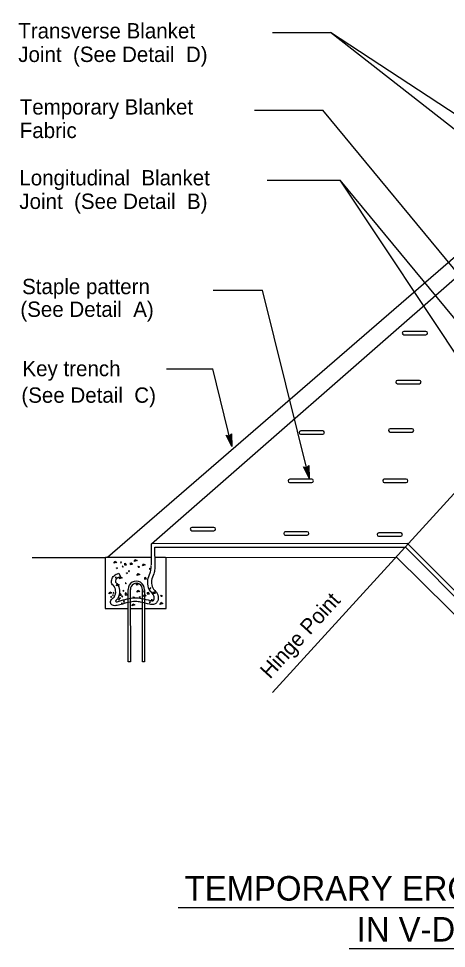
# Model space of a CAD drawing. Extents: x 6712486 to 6713732, y 1869200 to 1869925.
# Drawn here: x 6712488.9 to 6712663, y 1869199.8 to 1869578.2 of the extents above; entities that cross this region are included whole.
import ezdxf

# ---------------------------------------------------------------- set-up
doc = ezdxf.new("R2010")
doc.units = 0
for name, color, linetype in [('56 Stg 3 Anno', 7, 'Continuous'), ('57 Undefined', 7, 'Continuous'), ('60 Nongeo Data', 7, 'Continuous'), ('63 Undefined', 7, 'Continuous')]:
    doc.layers.add(name, color=color, linetype=linetype)

msp = doc.modelspace()

# ---------------------------------------------------------------- linework, layer by layer
at = {"layer": '56 Stg 3 Anno'}
for p, q in [((6712575.73, 1869404.07), (6712573.4, 1869408.62)), ((6712573.4, 1869408.62), (6712573.4, 1869408.62)), ((6712573.4, 1869408.62), (6712574.64, 1869408.26)), ((6712575.43, 1869405.19), (6712573.74, 1869408.51)), ((6712575.15, 1869406.29), (6712574.05, 1869408.44)), ((6712574.86, 1869407.41), (6712574.39, 1869408.32)), ((6712574.64, 1869408.26), (6712575.55, 1869409.18)), ((6712574.83, 1869408.45), (6712574.86, 1869407.41)), ((6712575.07, 1869408.67), (6712575.15, 1869406.29)), ((6712575.31, 1869408.93), (6712575.44, 1869405.18)), ((6712575.55, 1869409.18), (6712575.55, 1869409.18)), ((6712575.55, 1869409.18), (6712575.73, 1869404.07)), ((6712575.73, 1869404.07), (6712575.73, 1869404.07)), ((6712607.13, 1869391.15), (6712604.8, 1869395.7)), ((6712604.8, 1869395.7), (6712604.8, 1869395.7)), ((6712604.8, 1869395.7), (6712606.04, 1869395.34)), ((6712606.83, 1869392.27), (6712605.14, 1869395.59)), ((6712606.55, 1869393.37), (6712605.45, 1869395.52)), ((6712606.26, 1869394.49), (6712605.79, 1869395.41)), ((6712606.04, 1869395.34), (6712606.95, 1869396.26)), ((6712606.22, 1869395.54), (6712606.26, 1869394.49)), ((6712606.47, 1869395.75), (6712606.55, 1869393.37)), ((6712606.71, 1869396.01), (6712606.84, 1869392.26)), ((6712606.95, 1869396.26), (6712606.95, 1869396.26)), ((6712606.95, 1869396.26), (6712607.13, 1869391.15)), ((6712607.13, 1869391.15), (6712607.13, 1869391.15))]:
    msp.add_line(p, q, dxfattribs=at)
at = {"layer": '57 Undefined'}
for p, q in [((6712553.77, 1869216.45), (6712862.41, 1869216.45)), ((6712623.47, 1869199.8), (6712793.24, 1869199.8))]:
    msp.add_line(p, q, dxfattribs=at)
at = {"layer": '60 Nongeo Data'}
for p, q in [((6712525.01, 1869359), (6712778.34, 1869578.13)), ((6712592.16, 1869303.9), (6712842.3, 1869578.16)), ((6712592.17, 1869572.5), (6712615.77, 1869572.5)), ((6712716.02, 1869494.14), (6712615.77, 1869572.5)), ((6712724.97, 1869500.98), (6712615.77, 1869572.5)), ((6712584.88, 1869540.92), (6712612.7, 1869540.92)), ((6712695.74, 1869440.43), (6712612.7, 1869540.92)), ((6712590, 1869512.45), (6712619.78, 1869512.45)), ((6712707.85, 1869379.8), (6712619.78, 1869512.45)), ((6712711.19, 1869401.83), (6712619.78, 1869512.45)), ((6712542.99, 1869364.46), (6712696.56, 1869498.79)), ((6712568.01, 1869467.69), (6712588.18, 1869467.69)), ((6712607.13, 1869391.15), (6712588.18, 1869467.69)), ((6712654.67, 1869450.88), (6712645.71, 1869450.88)), ((6712645.65, 1869449.51), (6712654.67, 1869449.51)), ((6712549.02, 1869435.61), (6712567.92, 1869435.61)), ((6712575.73, 1869404.07), (6712567.92, 1869435.61)), ((6712652.01, 1869430.94), (6712643.06, 1869430.94)), ((6712643, 1869429.57), (6712652.01, 1869429.57)), ((6712603.64, 1869409.02), (6712612.66, 1869409.02)), ((6712612.66, 1869410.39), (6712603.7, 1869410.39)), ((6712640.02, 1869409.92), (6712649.04, 1869409.92)), ((6712649.04, 1869411.29), (6712640.09, 1869411.29)), ((6712599.17, 1869389.39), (6712608.18, 1869389.39)), ((6712608.18, 1869390.76), (6712599.23, 1869390.76)), ((6712637.66, 1869389.39), (6712646.67, 1869389.39)), ((6712646.67, 1869390.76), (6712637.72, 1869390.76)), ((6712568.38, 1869371.12), (6712559.43, 1869371.12)), ((6712559.37, 1869369.75), (6712568.38, 1869369.75)), ((6712597.38, 1869367.96), (6712606.39, 1869367.96)), ((6712606.39, 1869369.33), (6712597.44, 1869369.33)), ((6712635.39, 1869367.52), (6712644.41, 1869367.52)), ((6712644.41, 1869368.89), (6712635.46, 1869368.89)), ((6712524.31, 1869358.94), (6712542.88, 1869358.94)), ((6712527.71, 1869356.5), (6712528.17, 1869357.23)), ((6712528.9, 1869356.89), (6712527.71, 1869356.5)), ((6712528.05, 1869357.34), (6712528.9, 1869356.89)), ((6712530.67, 1869357.05), (6712530.36, 1869356.91)), ((6712530.36, 1869356.91), (6712530.41, 1869356.96)), ((6712530.41, 1869356.96), (6712530.64, 1869356.62)), ((6712530.64, 1869356.62), (6712530.7, 1869357.07)), ((6712531.38, 1869355.37), (6712531.07, 1869355.23)), ((6712531.07, 1869355.23), (6712531.12, 1869355.29)), ((6712531.12, 1869355.29), (6712531.35, 1869354.95)), ((6712531.35, 1869354.95), (6712531.41, 1869355.4)), ((6712532.4, 1869356.44), (6712531.84, 1869356.27)), ((6712531.95, 1869356.39), (6712531.95, 1869355.82)), ((6712531.95, 1869355.82), (6712532.85, 1869355.93)), ((6712532.85, 1869355.93), (6712532.4, 1869356.44)), ((6712534.77, 1869356.61), (6712534.21, 1869356.44)), ((6712534.32, 1869356.55), (6712534.32, 1869355.99)), ((6712534.32, 1869355.99), (6712535.22, 1869356.1)), ((6712535.22, 1869356.1), (6712534.77, 1869356.61)), ((6712535.9, 1869357.23), (6712536.35, 1869357.96)), ((6712537.09, 1869357.62), (6712535.9, 1869357.23)), ((6712536.24, 1869358.08), (6712537.09, 1869357.62)), ((6712537.37, 1869355.31), (6712537.65, 1869354.92)), ((6712537.37, 1869355.31), (6712537.99, 1869355.15)), ((6712539.29, 1869355.48), (6712539.74, 1869356.22)), ((6712540.47, 1869355.88), (6712539.29, 1869355.48)), ((6712539.63, 1869356.33), (6712540.47, 1869355.88)), ((6712544.66, 1869358.94), (6712548.62, 1869358.94)), ((6712528.99, 1869354.71), (6712528.68, 1869354.57)), ((6712528.68, 1869354.57), (6712528.74, 1869354.63)), ((6712528.74, 1869354.63), (6712528.96, 1869354.29)), ((6712528.96, 1869354.29), (6712529.02, 1869354.74)), ((6712533.05, 1869352.68), (6712532.74, 1869352.54)), ((6712532.74, 1869352.54), (6712532.8, 1869352.59)), ((6712532.8, 1869352.59), (6712533.03, 1869352.26)), ((6712533.03, 1869352.26), (6712533.08, 1869352.71)), ((6712534.09, 1869353.45), (6712533.59, 1869353.45)), ((6712533.64, 1869353.51), (6712533.81, 1869353)), ((6712533.81, 1869353), (6712534.09, 1869353.45)), ((6712537.05, 1869351.57), (6712537.51, 1869352.31)), ((6712538.24, 1869351.97), (6712537.05, 1869351.57)), ((6712537.39, 1869352.42), (6712538.24, 1869351.97)), ((6712537.65, 1869354.92), (6712538.05, 1869354.98)), ((6712538.05, 1869354.98), (6712537.99, 1869355.15)), ((6712542.37, 1869354.44), (6712542.06, 1869354.3)), ((6712542.11, 1869354.36), (6712542.34, 1869354.02)), ((6712542.34, 1869354.02), (6712542.39, 1869354.47)), ((6712542.39, 1869354.47), (6712542.34, 1869354.41)), ((6712528.54, 1869350.85), (6712528.23, 1869350.71)), ((6712528.23, 1869350.71), (6712528.28, 1869350.77)), ((6712528.28, 1869350.77), (6712528.51, 1869350.43)), ((6712528.51, 1869350.43), (6712528.56, 1869350.88)), ((6712528.63, 1869347.31), (6712529.08, 1869348.04)), ((6712529.81, 1869347.7), (6712528.63, 1869347.31)), ((6712528.97, 1869348.15), (6712529.81, 1869347.7)), ((6712529.85, 1869350.15), (6712530.3, 1869350.88)), ((6712531.03, 1869350.55), (6712529.85, 1869350.15)), ((6712530.19, 1869351), (6712531.03, 1869350.55)), ((6712532.6, 1869348.51), (6712532.29, 1869348.37)), ((6712532.29, 1869348.37), (6712532.34, 1869348.43)), ((6712532.34, 1869348.43), (6712532.57, 1869348.09)), ((6712532.57, 1869348.09), (6712532.62, 1869348.54)), ((6712537.14, 1869348.38), (6712536.58, 1869348.21)), ((6712536.69, 1869348.33), (6712536.69, 1869347.76)), ((6712536.69, 1869347.76), (6712537.59, 1869347.88)), ((6712537.59, 1869347.88), (6712537.14, 1869348.38)), ((6712540.53, 1869350.69), (6712539.97, 1869350.52)), ((6712540.08, 1869350.64), (6712540.08, 1869350.07)), ((6712540.08, 1869350.07), (6712540.98, 1869350.19)), ((6712540.98, 1869350.19), (6712540.53, 1869350.69)), ((6712525.67, 1869344.1), (6712526.12, 1869344.83)), ((6712526.85, 1869344.49), (6712525.67, 1869344.1)), ((6712526, 1869344.94), (6712526.85, 1869344.49)), ((6712527.68, 1869344.63), (6712527.37, 1869344.49)), ((6712527.37, 1869344.49), (6712527.43, 1869344.54)), ((6712527.43, 1869344.54), (6712527.65, 1869344.2)), ((6712527.65, 1869344.2), (6712527.71, 1869344.66)), ((6712530.35, 1869344.04), (6712529.79, 1869343.87)), ((6712529.9, 1869343.98), (6712529.9, 1869343.42)), ((6712530.8, 1869343.53), (6712530.35, 1869344.04)), ((6712531.58, 1869345.48), (6712531.27, 1869345.34)), ((6712531.33, 1869345.4), (6712531.55, 1869345.06)), ((6712531.55, 1869345.06), (6712531.61, 1869345.51)), ((6712531.61, 1869345.51), (6712531.55, 1869345.45)), ((6712532.72, 1869344.21), (6712532.16, 1869344.04)), ((6712532.27, 1869344.15), (6712532.27, 1869343.59)), ((6712532.6, 1869344.52), (6712532.29, 1869344.38)), ((6712532.34, 1869344.44), (6712532.57, 1869344.1)), ((6712532.57, 1869344.1), (6712532.63, 1869344.55)), ((6712532.63, 1869344.55), (6712532.57, 1869344.5)), ((6712533.17, 1869343.7), (6712532.72, 1869344.21)), ((6712533.52, 1869316.45), (6712533.51, 1869345.84)), ((6712534.36, 1869345.84), (6712534.38, 1869316.45)), ((6712537.04, 1869344.71), (6712537.49, 1869345.44)), ((6712538.22, 1869345.1), (6712537.04, 1869344.71)), ((6712537.38, 1869345.56), (6712538.22, 1869345.1)), ((6712539.29, 1869316.42), (6712539.27, 1869345.77)), ((6712539.99, 1869345.26), (6712539.68, 1869345.12)), ((6712539.68, 1869345.12), (6712539.74, 1869345.17)), ((6712539.74, 1869345.17), (6712539.96, 1869344.83)), ((6712539.96, 1869344.83), (6712540.02, 1869345.29)), ((6712540.13, 1869345.72), (6712540.11, 1869316.42)), ((6712541.72, 1869344.65), (6712541.16, 1869344.48)), ((6712541.27, 1869344.6), (6712541.27, 1869344.03)), ((6712541.27, 1869344.03), (6712542.18, 1869344.15)), ((6712542.18, 1869344.15), (6712541.72, 1869344.65)), ((6712542.34, 1869345.96), (6712542.79, 1869346.69)), ((6712544.1, 1869344.82), (6712543.53, 1869344.65)), ((6712543.64, 1869344.77), (6712543.64, 1869344.2)), ((6712543.64, 1869344.2), (6712544.55, 1869344.31)), ((6712544.55, 1869344.31), (6712544.1, 1869344.82)), ((6712526.66, 1869343), (6712526.35, 1869342.86)), ((6712526.35, 1869342.86), (6712526.4, 1869342.91)), ((6712526.4, 1869342.91), (6712526.63, 1869342.57)), ((6712526.63, 1869342.57), (6712526.69, 1869343.02)), ((6712527.37, 1869343.67), (6712527.06, 1869343.53)), ((6712527.06, 1869343.53), (6712527.11, 1869343.59)), ((6712527.11, 1869343.59), (6712527.34, 1869343.25)), ((6712527.34, 1869343.25), (6712527.39, 1869343.7)), ((6712529.83, 1869341.97), (6712529.52, 1869341.83)), ((6712529.52, 1869341.83), (6712529.57, 1869341.89)), ((6712529.57, 1869341.89), (6712529.8, 1869341.55)), ((6712529.8, 1869341.55), (6712529.86, 1869342)), ((6712530.2, 1869342.5), (6712529.89, 1869342.36)), ((6712529.89, 1869342.36), (6712529.95, 1869342.41)), ((6712529.9, 1869343.42), (6712530.8, 1869343.53)), ((6712529.95, 1869342.41), (6712530.17, 1869342.08)), ((6712530.17, 1869342.08), (6712530.23, 1869342.53)), ((6712531, 1869340.27), (6712530.69, 1869340.13)), ((6712530.69, 1869340.13), (6712530.75, 1869340.19)), ((6712530.75, 1869340.19), (6712530.98, 1869339.85)), ((6712531.18, 1869343.18), (6712530.86, 1869343.04)), ((6712530.86, 1869343.04), (6712530.92, 1869343.1)), ((6712530.92, 1869343.1), (6712531.15, 1869342.76)), ((6712530.98, 1869339.85), (6712531.03, 1869340.3)), ((6712531.15, 1869342.76), (6712531.2, 1869343.21)), ((6712532.04, 1869341.05), (6712531.54, 1869341.05)), ((6712531.59, 1869341.11), (6712531.76, 1869340.6)), ((6712531.76, 1869340.6), (6712532.04, 1869341.05)), ((6712532.27, 1869343.59), (6712533.17, 1869343.7)), ((6712535.32, 1869342.91), (6712535.6, 1869342.52)), ((6712535.32, 1869342.91), (6712535.94, 1869342.74)), ((6712535.6, 1869342.52), (6712536, 1869342.57)), ((6712536, 1869342.57), (6712535.94, 1869342.74)), ((6712538.32, 1869342.92), (6712538.01, 1869342.78)), ((6712538.01, 1869342.78), (6712538.06, 1869342.84)), ((6712538.06, 1869342.84), (6712538.29, 1869342.5)), ((6712538.29, 1869342.5), (6712538.34, 1869342.95)), ((6712539.66, 1869343.4), (6712539.34, 1869343.26)), ((6712539.4, 1869343.31), (6712539.63, 1869342.97)), ((6712539.63, 1869342.97), (6712539.68, 1869343.43)), ((6712539.68, 1869343.43), (6712539.63, 1869343.37)), ((6712540.7, 1869343.58), (6712540.39, 1869343.44)), ((6712540.39, 1869343.44), (6712540.45, 1869343.5)), ((6712540.45, 1869343.5), (6712540.67, 1869343.16)), ((6712540.67, 1869343.16), (6712540.73, 1869343.61)), ((6712542.38, 1869340.89), (6712542.07, 1869340.75)), ((6712542.07, 1869340.75), (6712542.12, 1869340.81)), ((6712542.12, 1869340.81), (6712542.35, 1869340.47)), ((6712542.35, 1869340.47), (6712542.41, 1869340.92)), ((6712543.42, 1869341.67), (6712542.91, 1869341.67)), ((6712542.97, 1869341.72), (6712543.14, 1869341.22)), ((6712543.14, 1869341.22), (6712543.42, 1869341.67)), ((6712546.38, 1869339.78), (6712546.83, 1869340.52)), ((6712547.56, 1869340.18), (6712546.38, 1869339.78)), ((6712546.69, 1869343.53), (6712546.97, 1869343.13)), ((6712546.69, 1869343.53), (6712547.31, 1869343.36)), ((6712546.72, 1869340.63), (6712547.56, 1869340.18)), ((6712546.97, 1869343.13), (6712547.37, 1869343.19)), ((6712547.37, 1869343.19), (6712547.31, 1869343.36)), ((6712535.01, 1869339.17), (6712535.46, 1869339.9)), ((6712536.19, 1869339.56), (6712535.01, 1869339.17)), ((6712535.34, 1869340.01), (6712536.19, 1869339.56)), ((6712534.38, 1869316.45), (6712533.52, 1869316.45)), ((6712540.11, 1869316.42), (6712539.29, 1869316.42))]:
    msp.add_line(p, q, dxfattribs=at)
for points in [[(6712542.95, 1869355.89), (6712542.94, 1869364.42)], [(6712674.37, 1869337.36), (6712647.2, 1869364.5), (6712542.99, 1869364.46)], [(6712544.42, 1869355.66), (6712544.4, 1869363.08), (6712646.3, 1869363.05), (6712673.19, 1869336.09)], [(6712494.39, 1869358.89), (6712524.16, 1869358.89), (6712524.13, 1869338.13), (6712533.51, 1869338.13)], [(6712540.11, 1869338.12), (6712548.89, 1869338.14), (6712548.92, 1869358.95)], [(6712548.67, 1869358.93), (6712642.64, 1869358.96), (6712717.35, 1869285.34), (6712792.86, 1869358.67), (6712892.16, 1869358.69), (6712892.17, 1869338.74), (6712901.48, 1869338.75)], [(6712534.37, 1869338.13), (6712539.29, 1869338.12)]]:
    msp.add_lwpolyline(points, dxfattribs=at)
for centre, radius, start, end in [((6712645.74, 1869450.19), 0.685, 92.5576, 270), ((6712654.67, 1869450.19), 0.686, 270, 90), ((6712643.09, 1869430.26), 0.685, 92.5576, 270), ((6712652.01, 1869430.26), 0.686, 270, 90), ((6712603.73, 1869409.71), 0.685, 92.5576, 270), ((6712612.66, 1869409.71), 0.686, 270, 90), ((6712640.12, 1869410.6), 0.685, 92.5576, 270), ((6712649.04, 1869410.6), 0.686, 270, 90), ((6712599.26, 1869390.07), 0.685, 92.5576, 270), ((6712608.18, 1869390.07), 0.686, 270, 90), ((6712637.75, 1869390.07), 0.685, 92.5576, 270), ((6712646.67, 1869390.07), 0.686, 270, 90), ((6712559.46, 1869370.43), 0.685, 92.5576, 270), ((6712568.38, 1869370.43), 0.686, 270, 90), ((6712597.47, 1869368.65), 0.685, 92.5576, 270), ((6712606.39, 1869368.65), 0.686, 270, 90), ((6712635.49, 1869368.2), 0.685, 92.5576, 270), ((6712644.41, 1869368.2), 0.686, 270, 90)]:
    msp.add_arc(centre, radius, start, end, dxfattribs=at)
for centre, major_axis in [((6712536.82, 1869345.96), (0, -3.31)), ((6712536.83, 1869345.93), (0, -2.45))]:
    msp.add_ellipse(centre, major_axis=major_axis, ratio=0.999991, start_param=1.510257, end_param=4.748244, dxfattribs=at)
at = {"layer": '63 Undefined'}
msp.add_line((6712529.69, 1869352.43), (6712530.37, 1869351.06), dxfattribs=at)
for points in [[(6712544.39, 1869355.52), (6712544.31, 1869354.27), (6712543.87, 1869352.21), (6712543.01, 1869349.5), (6712543.01, 1869348.31), (6712543.77, 1869346.04), (6712544.96, 1869344.74), (6712545.5, 1869343.65), (6712545.5, 1869341.27), (6712545.18, 1869340.68), (6712544.7, 1869340.1), (6712543.77, 1869339.75), (6712542.36, 1869339.86), (6712538.57, 1869340.73), (6712536.51, 1869340.95), (6712533.35, 1869340.55), (6712528.96, 1869339.37), (6712527.13, 1869339.41), (6712526.57, 1869339.82), (6712526.45, 1869340.08), (6712526.36, 1869340.46), (6712526.44, 1869341.38), (6712527.74, 1869342.79), (6712528.39, 1869345.39), (6712527.52, 1869347.45), (6712526.87, 1869348.2), (6712526.77, 1869349.81), (6712527.74, 1869351.45), (6712529.69, 1869352.43)], [(6712530.37, 1869351.06), (6712528.82, 1869350.29), (6712528.32, 1869349.44), (6712528.36, 1869348.81), (6712528.84, 1869348.26), (6712529.99, 1869345.51), (6712529.13, 1869342.04), (6712528.59, 1869341.45), (6712528.43, 1869341.3), (6712528.47, 1869340.9), (6712528.63, 1869340.84), (6712528.94, 1869340.88), (6712529.8, 1869341.11), (6712533.05, 1869342.06), (6712536.5, 1869342.48), (6712538.82, 1869342.24), (6712542.59, 1869341.38), (6712543.55, 1869341.3), (6712543.79, 1869341.39), (6712543.9, 1869341.53), (6712543.97, 1869341.66), (6712543.97, 1869343.29), (6712543.69, 1869343.86), (6712542.42, 1869345.25), (6712541.48, 1869348.06), (6712541.48, 1869349.74), (6712542.4, 1869352.6), (6712542.79, 1869354.48), (6712542.87, 1869355.62)]]:
    msp.add_spline(points, degree=3, dxfattribs=at)

# ---------------------------------------------------------------- texts
at = {"layer": '57 Undefined'}
for s, p in [('TEMPORARY EROSION CONTROL BLANKET', (6712556.51, 1869219.25)), ('IN V-DITCH OR SWALE', (6712626.49, 1869202.59))]:
    msp.add_text(s, height=9.9921, dxfattribs=at).set_placement(p)
at = {"layer": '60 Nongeo Data'}
for s, height, p in [('Transverse Blanket ', 6.2451, (6712488.76, 1869570.08)), ('Joint  (See Detail  D)', 6.2451, (6712488.76, 1869560.5)), ('Temporary Blanket ', 6.2451, (6712489.36, 1869539.12)), ('Fabric', 6.245, (6712489.36, 1869529.54)), ('Longitudinal  Blanket ', 6.2451, (6712489.19, 1869510.28)), ('Joint  (See Detail  B)', 6.2451, (6712489.19, 1869500.7)), ('Staple pattern', 6.2451, (6712490.32, 1869466.03)), ('(See Detail  A)', 6.2451, (6712489.61, 1869456.78)), ('Key trench', 6.245, (6712490.45, 1869432.65)), ('(See Detail  C)', 6.2451, (6712490.03, 1869421.83))]:
    msp.add_text(s, height=height, dxfattribs=at).set_placement(p)
msp.add_text('Hinge Point', height=6.2451, rotation=47.6341, dxfattribs=at).set_placement((6712591.17, 1869309.16))

doc.saveas('drawing.dxf')
